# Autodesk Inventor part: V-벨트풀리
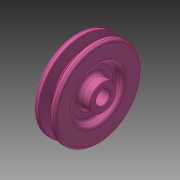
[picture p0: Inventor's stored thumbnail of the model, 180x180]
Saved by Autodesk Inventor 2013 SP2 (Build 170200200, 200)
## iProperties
Created: 2015-11
Part Number: V-벨트풀리
Material: 강철, 탄소
Document SubType Name: Modeling
Designer: mduedu
Density: 1 g/cm^3
Author: mduedu
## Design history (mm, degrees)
sketch "스케치1"
  geometry: L1 (-9.5, 0)-(9.5, 0); L2 (0, 0)-(0, 37.7); L3 (-4.825, 37.7)-(-9.5, 37.7); L4 (-9.5, 37.7)-(-9.5, 0); L5 (0, 28.7)-(-2.074, 28.7); L6 (-2.074, 28.7)-(-4.825, 37.7); L7 (4.825, 37.7)-(9.5, 37.7); L8 (9.5, 37.7)-(9.5, 0); L9 (0, 28.7)-(2.074, 28.7); L10 (2.074, 28.7)-(4.825, 37.7); L11 (-9.5, 35)-(9.5, 35); 3 further points
  constraints: 22 end point, 7 point on line, 4 perpendicular, 3 symmetric about line, 1 coincident, 1 horizontal, 1 horizontal alignment, 1 midpoint, 1 vertical
  dimensions: "d0" = 19 distance of L1.start L1.end; "d2" = 75.4 diameter of L2.end L1 (derived); "d3" = 34 deg angle of L10 L6; "d4" = 6.3 distance between parallel lines of L11 L9; "d5" = 2.7 distance between parallel lines of L7 L11; "d6" = 8 distance of point (4, 35) point (-4, 35); "d7" = 70 diameter of L11 L1
revolve "회전1" sketch "스케치1" stored, may be unused: angle "d8" = 90 deg
sketch "스케치2"
  geometry: C1 r 22.5 at (0, 0); C2 r 12.5 at (0, 0); C3 r 37.7 at (0, 0) reference; 1 further point
  constraints: 2 centre point, 2 coincident
  dimensions: "d35" = 15.2 radial gap between concentric circles of C3 C1 (computed from d5); "d36" = 10 radial gap between concentric circles of C1 C2
extrude "돌출1" cut sketch "스케치2" distance "d11" = 6; taper "d12" = 0 deg
fillet "모깎기1" dims "d13" = 3
feature "면 이동1"
fillet "모깎기2" dims "d14" = 3
fillet "모깎기3" dims "d15" = 1, "d16" = 0.5, "d17" = 2
hole "구멍1" diameter "d20" = 12; stored, may be unused: countersink angle "d24" = 90 deg, drill point angle "d26" = 118 deg; dims "d21" = 6, "d22" = 4, "d23" = 2, "d25" = 8, "d37" = 10, "d38" = 10
sketch "스케치3"
  geometry: L1 (-2, 0)-(2, 0); L2 (2, 0)-(2, 7.8); L3 (2, 7.8)-(-2, 7.8); L4 (-2, 7.8)-(-2, 0); C1 r 12.5 at (0, 0) reference; 2 further points
  constraints: 8 end point, 2 coincident, 2 parallel, 1 horizontal, 1 midpoint, 1 perpendicular
  dimensions: "d27" = 4 distance of L2.end L3.end; "d29" = 7.8 distance of L3.end L1.start
extrude "돌출2" cut sketch "스케치3" stored distance "d30" = 6; taper "d31" = 0 deg
chamfer "모따기1" distance "d32" = 0.5; stored, may be unused: second distance "d33" = 2, angle "d34" = 45 deg
node "솔리드1"
mirror "대칭1"
